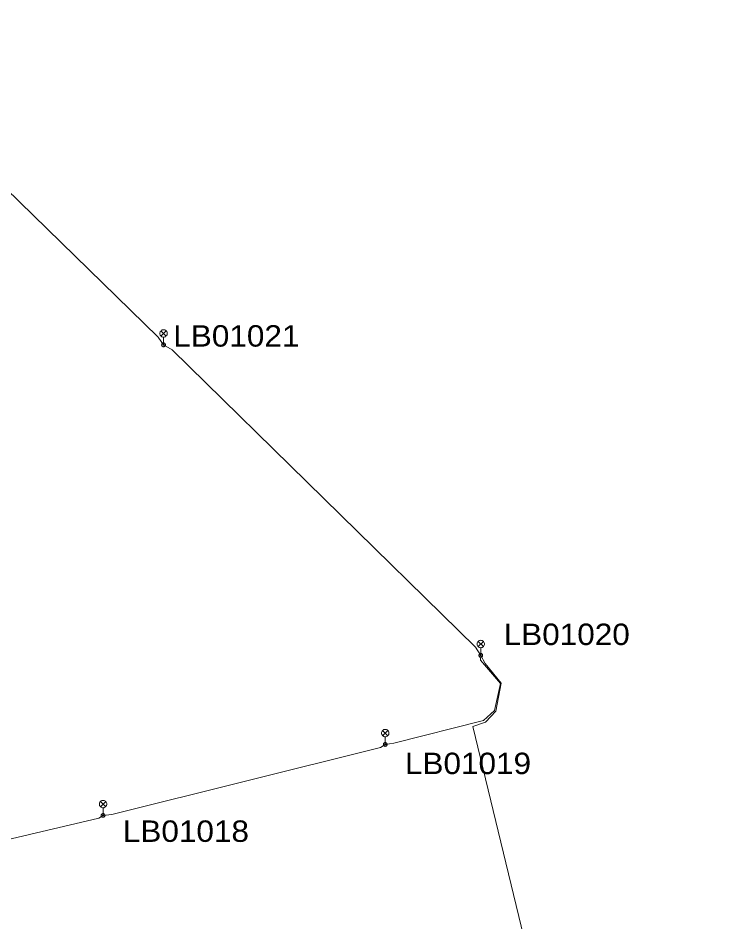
# Model space of a CAD drawing. Extents: x -688049 to -687261, y -973611 to -973038.
# Drawn here: x -687428.6 to -687356.5, y -973229.3 to -973137.9 of the extents above; entities that cross this region are included whole.
import ezdxf

# ---------------------------------------------------------------- set-up
doc = ezdxf.new("R2010")
doc.units = 0
doc.header["$LTSCALE"] = 0.87
doc.layers.add('1', color=7, linetype='Continuous', lineweight=13)

msp = doc.modelspace()

# ---------------------------------------------------------------- linework, layer by layer
at = {"layer": '1'}
for p, q in [((-687414.115, -973169.505), (-687413.585, -973170.035)), ((-687414.115, -973170.035), (-687413.585, -973169.505)), ((-687413.85, -973170.92), (-687413.85, -973170.145)), ((-687382.015, -973200.915), (-687381.485, -973201.445)), ((-687382.015, -973201.445), (-687381.485, -973200.915)), ((-687381.75, -973202.33), (-687381.75, -973201.555)), ((-687391.685, -973209.925), (-687391.155, -973210.455)), ((-687391.685, -973210.455), (-687391.155, -973209.925)), ((-687391.42, -973211.34), (-687391.42, -973210.565)), ((-687420.235, -973217.105), (-687419.705, -973217.635)), ((-687420.235, -973217.635), (-687419.705, -973217.105)), ((-687419.97, -973218.52), (-687419.97, -973217.745))]:
    msp.add_line(p, q, dxfattribs=at)
for points in [[(-687447.42, -973137.87), (-687446.715, -973138.656), (-687414.387, -973170.158), (-687413.85, -973170.92)], [(-687413.85, -973170.92), (-687412.976, -973171.433), (-687382.28, -973201.508), (-687381.75, -973202.33)], [(-687381.735, -973202.351), (-687381.774, -973202.81), (-687379.767, -973205.186), (-687380.363, -973207.911), (-687381.478, -973208.914), (-687390.564, -973211.212), (-687391.42, -973211.34)], [(-687356.54, -973246.87), (-687357.499, -973246.115), (-687360.447, -973243.857), (-687364.449, -973242.409), (-687368.798, -973241.637), (-687374.546, -973242.515), (-687382.562, -973209.507), (-687381.261, -973209.073), (-687380.24, -973207.97), (-687379.671, -973205.153), (-687381.293, -973203.137), (-687381.75, -973202.33)], [(-687391.42, -973211.34), (-687391.89, -973211.635), (-687419.098, -973218.433), (-687419.97, -973218.52)], [(-687420.016, -973218.543), (-687420.383, -973218.795), (-687456.084, -973227.179), (-687457.55, -973225.75), (-687457.55, -973224.975)]]:
    msp.add_lwpolyline(points, dxfattribs=at)
for points in [[(-687413.475, -973169.77), (-687413.481, -973169.705), (-687413.498, -973169.642), (-687413.525, -973169.582), (-687413.563, -973169.529), (-687413.609, -973169.483), (-687413.662, -973169.445), (-687413.722, -973169.418), (-687413.785, -973169.401), (-687413.85, -973169.395), (-687413.915, -973169.401), (-687413.978, -973169.418), (-687414.038, -973169.445), (-687414.091, -973169.483), (-687414.137, -973169.529), (-687414.175, -973169.582), (-687414.202, -973169.642), (-687414.219, -973169.705), (-687414.225, -973169.77), (-687414.219, -973169.835), (-687414.202, -973169.898), (-687414.175, -973169.958), (-687414.137, -973170.011), (-687414.091, -973170.057), (-687414.038, -973170.095), (-687413.978, -973170.122), (-687413.915, -973170.139), (-687413.85, -973170.145), (-687413.785, -973170.139), (-687413.722, -973170.122), (-687413.662, -973170.095), (-687413.609, -973170.057), (-687413.563, -973170.011), (-687413.525, -973169.958), (-687413.498, -973169.898), (-687413.481, -973169.835)], [(-687413.66, -973170.92), (-687413.663, -973170.887), (-687413.671, -973170.855), (-687413.685, -973170.825), (-687413.704, -973170.798), (-687413.728, -973170.774), (-687413.755, -973170.755), (-687413.785, -973170.741), (-687413.817, -973170.733), (-687413.85, -973170.73), (-687413.883, -973170.733), (-687413.915, -973170.741), (-687413.945, -973170.755), (-687413.972, -973170.774), (-687413.996, -973170.798), (-687414.015, -973170.825), (-687414.029, -973170.855), (-687414.037, -973170.887), (-687414.04, -973170.92), (-687414.037, -973170.953), (-687414.029, -973170.985), (-687414.015, -973171.015), (-687413.996, -973171.042), (-687413.972, -973171.066), (-687413.945, -973171.085), (-687413.915, -973171.099), (-687413.883, -973171.107), (-687413.85, -973171.11), (-687413.817, -973171.107), (-687413.785, -973171.099), (-687413.755, -973171.085), (-687413.728, -973171.066), (-687413.704, -973171.042), (-687413.685, -973171.015), (-687413.671, -973170.985), (-687413.663, -973170.953)], [(-687413.8, -973170.92), (-687413.801, -973170.911), (-687413.803, -973170.903), (-687413.807, -973170.895), (-687413.812, -973170.888), (-687413.818, -973170.882), (-687413.825, -973170.877), (-687413.833, -973170.873), (-687413.841, -973170.871), (-687413.85, -973170.87), (-687413.859, -973170.871), (-687413.867, -973170.873), (-687413.875, -973170.877), (-687413.882, -973170.882), (-687413.888, -973170.888), (-687413.893, -973170.895), (-687413.897, -973170.903), (-687413.899, -973170.911), (-687413.9, -973170.92), (-687413.899, -973170.929), (-687413.897, -973170.937), (-687413.893, -973170.945), (-687413.888, -973170.952), (-687413.882, -973170.958), (-687413.875, -973170.963), (-687413.867, -973170.967), (-687413.859, -973170.969), (-687413.85, -973170.97), (-687413.841, -973170.969), (-687413.833, -973170.967), (-687413.825, -973170.963), (-687413.818, -973170.958), (-687413.812, -973170.952), (-687413.807, -973170.945), (-687413.803, -973170.937), (-687413.801, -973170.929)], [(-687381.375, -973201.18), (-687381.381, -973201.115), (-687381.398, -973201.052), (-687381.425, -973200.992), (-687381.463, -973200.939), (-687381.509, -973200.893), (-687381.562, -973200.855), (-687381.622, -973200.828), (-687381.685, -973200.811), (-687381.75, -973200.805), (-687381.815, -973200.811), (-687381.878, -973200.828), (-687381.938, -973200.855), (-687381.991, -973200.893), (-687382.037, -973200.939), (-687382.075, -973200.992), (-687382.102, -973201.052), (-687382.119, -973201.115), (-687382.125, -973201.18), (-687382.119, -973201.245), (-687382.102, -973201.308), (-687382.075, -973201.367), (-687382.037, -973201.421), (-687381.991, -973201.467), (-687381.938, -973201.505), (-687381.878, -973201.532), (-687381.815, -973201.549), (-687381.75, -973201.555), (-687381.685, -973201.549), (-687381.622, -973201.532), (-687381.562, -973201.505), (-687381.509, -973201.467), (-687381.463, -973201.421), (-687381.425, -973201.367), (-687381.398, -973201.308), (-687381.381, -973201.245)], [(-687381.56, -973202.33), (-687381.563, -973202.297), (-687381.571, -973202.265), (-687381.585, -973202.235), (-687381.604, -973202.208), (-687381.628, -973202.184), (-687381.655, -973202.165), (-687381.685, -973202.151), (-687381.717, -973202.143), (-687381.75, -973202.14), (-687381.783, -973202.143), (-687381.815, -973202.151), (-687381.845, -973202.165), (-687381.872, -973202.184), (-687381.896, -973202.208), (-687381.915, -973202.235), (-687381.929, -973202.265), (-687381.937, -973202.297), (-687381.94, -973202.33), (-687381.937, -973202.363), (-687381.929, -973202.395), (-687381.915, -973202.425), (-687381.896, -973202.452), (-687381.872, -973202.476), (-687381.845, -973202.495), (-687381.815, -973202.509), (-687381.783, -973202.517), (-687381.75, -973202.52), (-687381.717, -973202.517), (-687381.685, -973202.509), (-687381.655, -973202.495), (-687381.628, -973202.476), (-687381.604, -973202.452), (-687381.585, -973202.425), (-687381.571, -973202.395), (-687381.563, -973202.363)], [(-687381.7, -973202.33), (-687381.701, -973202.321), (-687381.703, -973202.313), (-687381.707, -973202.305), (-687381.712, -973202.298), (-687381.718, -973202.292), (-687381.725, -973202.287), (-687381.733, -973202.283), (-687381.741, -973202.281), (-687381.75, -973202.28), (-687381.759, -973202.281), (-687381.767, -973202.283), (-687381.775, -973202.287), (-687381.782, -973202.292), (-687381.788, -973202.298), (-687381.793, -973202.305), (-687381.797, -973202.313), (-687381.799, -973202.321), (-687381.8, -973202.33), (-687381.799, -973202.339), (-687381.797, -973202.347), (-687381.793, -973202.355), (-687381.788, -973202.362), (-687381.782, -973202.368), (-687381.775, -973202.373), (-687381.767, -973202.377), (-687381.759, -973202.379), (-687381.75, -973202.38), (-687381.741, -973202.379), (-687381.733, -973202.377), (-687381.725, -973202.373), (-687381.718, -973202.368), (-687381.712, -973202.362), (-687381.707, -973202.355), (-687381.703, -973202.347), (-687381.701, -973202.339)], [(-687391.045, -973210.19), (-687391.051, -973210.125), (-687391.068, -973210.062), (-687391.095, -973210.003), (-687391.133, -973209.949), (-687391.179, -973209.903), (-687391.232, -973209.865), (-687391.292, -973209.838), (-687391.355, -973209.821), (-687391.42, -973209.815), (-687391.485, -973209.821), (-687391.548, -973209.838), (-687391.608, -973209.865), (-687391.661, -973209.903), (-687391.707, -973209.949), (-687391.745, -973210.003), (-687391.772, -973210.062), (-687391.789, -973210.125), (-687391.795, -973210.19), (-687391.789, -973210.255), (-687391.772, -973210.318), (-687391.745, -973210.378), (-687391.707, -973210.431), (-687391.661, -973210.477), (-687391.608, -973210.515), (-687391.548, -973210.542), (-687391.485, -973210.559), (-687391.42, -973210.565), (-687391.355, -973210.559), (-687391.292, -973210.542), (-687391.232, -973210.515), (-687391.179, -973210.477), (-687391.133, -973210.431), (-687391.095, -973210.378), (-687391.068, -973210.318), (-687391.051, -973210.255)], [(-687391.23, -973211.34), (-687391.233, -973211.307), (-687391.241, -973211.275), (-687391.255, -973211.245), (-687391.274, -973211.218), (-687391.298, -973211.194), (-687391.325, -973211.175), (-687391.355, -973211.161), (-687391.387, -973211.153), (-687391.42, -973211.15), (-687391.453, -973211.153), (-687391.485, -973211.161), (-687391.515, -973211.175), (-687391.542, -973211.194), (-687391.566, -973211.218), (-687391.585, -973211.245), (-687391.599, -973211.275), (-687391.607, -973211.307), (-687391.61, -973211.34), (-687391.607, -973211.373), (-687391.599, -973211.405), (-687391.585, -973211.435), (-687391.566, -973211.462), (-687391.542, -973211.486), (-687391.515, -973211.505), (-687391.485, -973211.519), (-687391.453, -973211.527), (-687391.42, -973211.53), (-687391.387, -973211.527), (-687391.355, -973211.519), (-687391.325, -973211.505), (-687391.298, -973211.486), (-687391.274, -973211.462), (-687391.255, -973211.435), (-687391.241, -973211.405), (-687391.233, -973211.373)], [(-687391.37, -973211.34), (-687391.371, -973211.331), (-687391.373, -973211.323), (-687391.377, -973211.315), (-687391.382, -973211.308), (-687391.388, -973211.302), (-687391.395, -973211.297), (-687391.403, -973211.293), (-687391.411, -973211.291), (-687391.42, -973211.29), (-687391.429, -973211.291), (-687391.437, -973211.293), (-687391.445, -973211.297), (-687391.452, -973211.302), (-687391.458, -973211.308), (-687391.463, -973211.315), (-687391.467, -973211.323), (-687391.469, -973211.331), (-687391.47, -973211.34), (-687391.469, -973211.349), (-687391.467, -973211.357), (-687391.463, -973211.365), (-687391.458, -973211.372), (-687391.452, -973211.378), (-687391.445, -973211.383), (-687391.437, -973211.387), (-687391.429, -973211.389), (-687391.42, -973211.39), (-687391.411, -973211.389), (-687391.403, -973211.387), (-687391.395, -973211.383), (-687391.388, -973211.378), (-687391.382, -973211.372), (-687391.377, -973211.365), (-687391.373, -973211.357), (-687391.371, -973211.349)], [(-687419.595, -973217.37), (-687419.601, -973217.305), (-687419.618, -973217.242), (-687419.645, -973217.182), (-687419.683, -973217.129), (-687419.729, -973217.083), (-687419.782, -973217.045), (-687419.842, -973217.018), (-687419.905, -973217.001), (-687419.97, -973216.995), (-687420.035, -973217.001), (-687420.098, -973217.018), (-687420.158, -973217.045), (-687420.211, -973217.083), (-687420.257, -973217.129), (-687420.295, -973217.182), (-687420.322, -973217.242), (-687420.339, -973217.305), (-687420.345, -973217.37), (-687420.339, -973217.435), (-687420.322, -973217.498), (-687420.295, -973217.558), (-687420.257, -973217.611), (-687420.211, -973217.657), (-687420.158, -973217.695), (-687420.098, -973217.722), (-687420.035, -973217.739), (-687419.97, -973217.745), (-687419.905, -973217.739), (-687419.842, -973217.722), (-687419.782, -973217.695), (-687419.729, -973217.657), (-687419.683, -973217.611), (-687419.645, -973217.558), (-687419.618, -973217.498), (-687419.601, -973217.435)], [(-687419.78, -973218.52), (-687419.783, -973218.487), (-687419.791, -973218.455), (-687419.805, -973218.425), (-687419.824, -973218.398), (-687419.848, -973218.374), (-687419.875, -973218.355), (-687419.905, -973218.341), (-687419.937, -973218.333), (-687419.97, -973218.33), (-687420.003, -973218.333), (-687420.035, -973218.341), (-687420.065, -973218.355), (-687420.092, -973218.374), (-687420.116, -973218.398), (-687420.135, -973218.425), (-687420.149, -973218.455), (-687420.157, -973218.487), (-687420.16, -973218.52), (-687420.157, -973218.553), (-687420.149, -973218.585), (-687420.135, -973218.615), (-687420.116, -973218.642), (-687420.092, -973218.666), (-687420.065, -973218.685), (-687420.035, -973218.699), (-687420.003, -973218.707), (-687419.97, -973218.71), (-687419.937, -973218.707), (-687419.905, -973218.699), (-687419.875, -973218.685), (-687419.848, -973218.666), (-687419.824, -973218.642), (-687419.805, -973218.615), (-687419.791, -973218.585), (-687419.783, -973218.553)], [(-687419.92, -973218.52), (-687419.921, -973218.511), (-687419.923, -973218.503), (-687419.927, -973218.495), (-687419.932, -973218.488), (-687419.938, -973218.482), (-687419.945, -973218.477), (-687419.953, -973218.473), (-687419.961, -973218.471), (-687419.97, -973218.47), (-687419.979, -973218.471), (-687419.987, -973218.473), (-687419.995, -973218.477), (-687420.002, -973218.482), (-687420.008, -973218.488), (-687420.013, -973218.495), (-687420.017, -973218.503), (-687420.019, -973218.511), (-687420.02, -973218.52), (-687420.019, -973218.529), (-687420.017, -973218.537), (-687420.013, -973218.545), (-687420.008, -973218.552), (-687420.002, -973218.558), (-687419.995, -973218.563), (-687419.987, -973218.567), (-687419.979, -973218.569), (-687419.97, -973218.57), (-687419.961, -973218.569), (-687419.953, -973218.567), (-687419.945, -973218.563), (-687419.938, -973218.558), (-687419.932, -973218.552), (-687419.927, -973218.545), (-687419.923, -973218.537), (-687419.921, -973218.529)]]:
    msp.add_lwpolyline(points, close=True, dxfattribs=at)

# ---------------------------------------------------------------- texts
at = {"layer": '1', "width": 1.1}
for s, p in [('LB01021', (-687412.862, -973171.1)), ('LB01020', (-687379.434, -973201.285)), ('LB01019', (-687389.422, -973214.338)), ('LB01018', (-687417.969, -973221.193))]:
    msp.add_text(s, height=2.167, dxfattribs=at).set_placement(p)

doc.saveas('drawing.dxf')
